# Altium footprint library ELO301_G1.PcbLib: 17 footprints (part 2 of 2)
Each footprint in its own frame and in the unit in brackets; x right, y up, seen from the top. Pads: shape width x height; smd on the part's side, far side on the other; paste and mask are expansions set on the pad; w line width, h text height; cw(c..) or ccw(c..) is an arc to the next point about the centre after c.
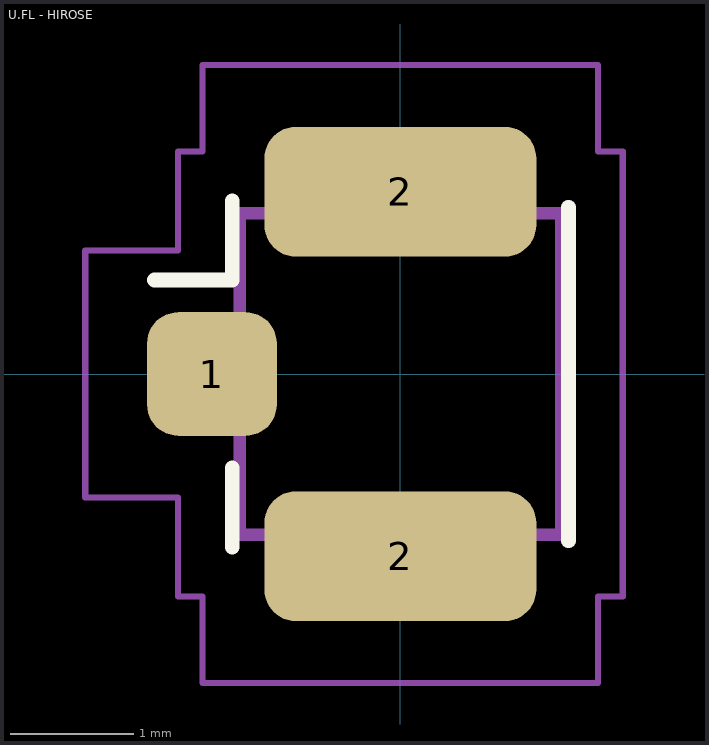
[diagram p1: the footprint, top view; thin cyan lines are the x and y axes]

## U.FL - HIROSE [mm] "Hirose U.FL Coaxial (https://www.hirose.com/en/product/document?clcode=CL0331-0472-2-01&productname=U.FL-R-SMT-1(01)&series=U.FL&documenttype=2DDrawing&lang=en&documentid=0000940668)"
pads (3):
  rrect50% 1.05x1 smd: 1(-1.525,0)
  rrect48% 2.2x1.05 smd: 2(0,-1.475) 2(0,1.475)
Top Overlay:
  lines w0.12: -1.99,0.76 -1.36,0.76 -1.36,1.4 ; -1.36,-1.4 -1.36,-0.76 ; 1.36,-1.35 1.36,1.35
Mechanical 13:
  lines w0.1: -1.55,-0.3 -1.55,0.15 -1.4,0.3 -1.3,0.3 -1.3,1.3 -0.9,1.3 -0.9,1.5 0.9,1.5 0.9,1.3 1.3,1.3 1.3,-1.3 0.9,-1.3 0.9,-1.5 -0.9,-1.5 -0.9,-1.3 -1.3,-1.3 -1.3,-0.3 -1.55,-0.3
Mechanical 15:
  lines w0.05: -2.55,-1 -1.8,-1 -1.8,-1.8 -1.6,-1.8 -1.6,-2.5 1.6,-2.5 1.6,-1.8 1.8,-1.8 1.8,1.8 1.6,1.8 1.6,2.5 -1.6,2.5 -1.6,1.8 -1.8,1.8 -1.8,1 -2.55,1 -2.55,-1
Mechanical 29:
  text ".Designator" at -0.508,-0.102 h0.25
